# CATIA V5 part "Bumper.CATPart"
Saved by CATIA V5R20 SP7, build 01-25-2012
Part number: Bumper
Bounding box of the stored display mesh (mm): x -300 to 25, y -507.762 to 507.762, z -50 to 50
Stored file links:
  E:\#03 University\#02 영남 이공대\#01 2021\#02 여름 방학\#01 Documents\K-Move Page02 ASD01\Bumper.CATPart

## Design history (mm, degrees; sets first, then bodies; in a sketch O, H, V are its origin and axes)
Set1 "Reference Data"
  Point1 "Center Point": (0, 0, 0)
Body1 (main body)
Body2
  Sketch1 "Center Curve" on xy-plane, origin (0, 0, 0), H (0, 1, 0), V (-1, 0, 0)
    line L1 (0, 0) -> (376.3932, 0)
    point P1 (400, 0)
    line L2 (421.1146, 10.5573) -> (500, 50)
    point P2 (500, 50)
    arc A1 centre (376.3932, 100) radius 100 from (376.3932, 0) to (421.1146, 10.5573) ccw
    distance V P1 = 400
    distance P1 P2 H = 100
    distance L1 P2 = 50
    radius A1 = 100
    horizontal: L1 H
    coincidence: L1 P1, L2 P1
    tangency: A1 L1, A1 L2
  Sketch2 "Profile Curve" on zx-plane, origin (0, 0, 0), H (-1, 0, 0), V (0, 0, 1)
    line L1 (25, 50) -> (25, -50)
    line L2 (25, -50) -> (-25, -50)
    line L3 (-25, -50) -> (-25, 50)
    line L4 (-25, 50) -> (25, 50)
    distance L3 L1 = 50
    distance L4 L2 = 100
    vertical: L1 V, L3 V
    horizontal: L2 H, L4 H
    equidistance: L1 L3 O, L2 L4 O
  Rib1: profile Sketch2, centre curve Sketch1
  Fillet1: radius 10, on edge [face of Rib1 | face of Rib1] (x4)
  Fillet2: radius 10, on face of Rib1
  Sketch3 on yz-plane, origin (0, 0, 0), H (0, 1, 0), V (0, 0, 1)
    circle A1 centre (150, 0) radius 15
    point P1 (150, 0)
    distance V P1 = 150
    radius A1 = 15
    coincidence: P1 H
  Pad1: profile Sketch3, direction (-1, 0, 0), length 300
  Mirror1: of the body so far, about zx-plane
